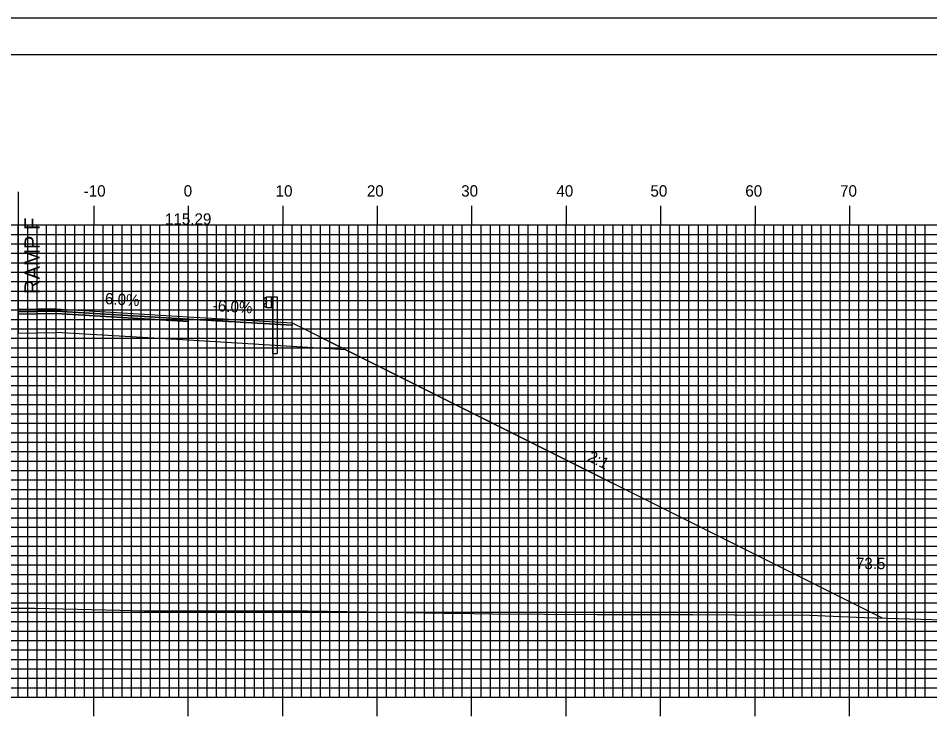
# Model space of a CAD drawing. Extents: x 855690 to 856034, y 364366 to 364586.
# Drawn here: x 855838.3 to 855934.8, y 364511.3 to 364585.7 of the extents above; entities that cross this region are included whole.
import ezdxf

# ---------------------------------------------------------------- set-up
doc = ezdxf.new("R2010")
doc.units = 0
for name, color, linetype in [('ANNOTATION', 7, 'Continuous'), ('BORDER', 7, 'Continuous'), ('D_Guardrail_Beam_Rt', 7, 'Continuous'), ('D_Roadway_Centerline', 7, 'Continuous'), ('D_Roadway_Centerline_Text', 7, 'Continuous'), ('D_Roadway_Edge_Shoulder', 7, 'Continuous'), ('D_Roadway_Edge_TW', 7, 'Continuous'), ('D_Roadway_Pavement', 7, 'Continuous'), ('D_Roadway_SlopeLines', 7, 'Continuous'), ('D_Roadway_SubGrade', 7, 'Continuous'), ('D_Text_Standard', 7, 'Continuous'), ('H_V ANNOTATION', 7, 'Continuous'), ('MAJOR', 7, 'Continuous'), ('MINOR', 7, 'Continuous'), ('PLOT BOUNDARY', 7, 'Continuous'), ('S_Roadway_Centerline', 7, 'Continuous')]:
    doc.layers.add(name, color=color, linetype=linetype)

msp = doc.modelspace()

# ---------------------------------------------------------------- linework, layer by layer
at = {"layer": 'BORDER'}
msp.add_lwpolyline([(855706.683, 364371.787), (856026.683, 364371.787), (856026.683, 364581.787), (855706.683, 364581.787)], close=True, dxfattribs=at)
at = {"layer": 'D_Guardrail_Beam_Rt'}
for p, q in [((855864.464, 364556.072), (855864.32, 364555.972)), ((855864.32, 364555.829), (855864.516, 364555.692)), ((855864.554, 364556.093), (855864.48, 364556.078)), ((855864.554, 364556.176), (855865.241, 364556.176)), ((855864.554, 364555.01), (855864.554, 364556.176)), ((855865.075, 364556.176), (855865.075, 364555.01)), ((855865.179, 364556.176), (855865.179, 364555.01)), ((855865.241, 364556.176), (855865.712, 364556.176)), ((855865.241, 364556.176), (855865.241, 364555.01)), ((855865.712, 364556.176), (855865.712, 364550.176)), ((855864.516, 364555.493), (855864.32, 364555.357)), ((855864.32, 364555.214), (855864.464, 364555.114)), ((855864.48, 364555.107), (855864.554, 364555.093)), ((855864.549, 364555.628), (855864.549, 364555.558)), ((855865.241, 364555.01), (855864.554, 364555.01)), ((855865.221, 364550.176), (855865.221, 364555.01)), ((855865.221, 364550.176), (855865.712, 364550.176))]:
    msp.add_line(p, q, dxfattribs=at)
for centre, major_axis, start_param, end_param in [((855864.371, 364555.9), (-0.0877, 0), 5.323254, 7.243116), ((855864.488, 364556.038), (-0.0417, 0), 4.907132, 5.323254), ((855864.371, 364555.286), (-0.0877, 0), 5.323254, 7.243116), ((855864.488, 364555.148), (-0.0417, 0), 0.959931, 1.376053), ((855864.471, 364555.628), (0.0789, 0), 0, 0.959931), ((855864.471, 364555.558), (0.0789, 0), 5.323254, 6.283185)]:
    msp.add_ellipse(centre, major_axis=major_axis, ratio=0.995501, start_param=start_param, end_param=end_param, dxfattribs=at)
at = {"layer": 'D_Roadway_Centerline'}
msp.add_lwpolyline([(855838.283, 364554.833), (855842.283, 364554.913), (855856.283, 364554.073), (855864.283, 364553.593), (855867.283, 364553.413), (855872.965, 364550.572), (855929.752, 364522.178)], dxfattribs=at)
at = {"layer": 'D_Roadway_Edge_Shoulder'}
for points in [[(855842.283, 364554.913), (855838.283, 364554.833), (855838.283, 364554.583), (855842.283, 364554.663)], [(855856.283, 364554.073), (855864.283, 364553.593), (855864.283, 364553.593), (855867.283, 364553.413), (855867.283, 364553.163), (855856.283, 364553.823)]]:
    msp.add_lwpolyline(points, close=True, dxfattribs=at)
at = {"layer": 'D_Roadway_Edge_TW'}
msp.add_lwpolyline([(855842.283, 364554.913), (855856.283, 364554.073), (855856.283, 364553.823), (855842.283, 364554.663)], close=True, dxfattribs=at)
at = {"layer": 'D_Roadway_Pavement'}
for points in [[(855842.283, 364554.663), (855838.283, 364554.583), (855838.283, 364554.333), (855842.283, 364554.413)], [(855842.283, 364554.663), (855856.283, 364553.823), (855856.283, 364553.573), (855842.283, 364554.413)]]:
    msp.add_lwpolyline(points, close=True, dxfattribs=at)
msp.add_lwpolyline([(855856.283, 364553.823), (855856.283, 364553.573)], dxfattribs=at)
msp.add_lwpolyline([(855856.283, 364553.823), (855856.283, 364553.573)], dxfattribs=at)
at = {"layer": 'D_Roadway_SlopeLines'}
msp.add_lwpolyline([(855867.283, 364553.413), (855929.752, 364522.178)], dxfattribs=at)
at = {"layer": 'D_Roadway_SubGrade'}
msp.add_line((855838.283, 364567.29), (855838.283, 364552.333), dxfattribs=at)
for points in [[(855842.283, 364554.413), (855838.283, 364554.333), (855838.283, 364554.583), (855838.283, 364554.833), (855838.283, 364552.333), (855842.283, 364552.413)], [(855842.283, 364554.413), (855856.283, 364553.573), (855856.283, 364551.573), (855842.283, 364552.413)], [(855856.283, 364553.573), (855856.283, 364553.823), (855867.283, 364553.163), (855867.283, 364553.413), (855872.965, 364550.572), (855856.283, 364551.573)]]:
    msp.add_lwpolyline(points, close=True, dxfattribs=at)
at = {"layer": 'MAJOR'}
for p, q in [((855846.283, 364565.791), (855846.283, 364563.787)), ((855856.283, 364565.791), (855856.283, 364563.787)), ((855866.283, 364565.791), (855866.283, 364563.787)), ((855876.283, 364565.791), (855876.283, 364563.787)), ((855886.283, 364565.791), (855886.283, 364563.787)), ((855896.283, 364565.791), (855896.283, 364563.787)), ((855906.283, 364565.791), (855906.283, 364563.787)), ((855916.283, 364565.791), (855916.283, 364563.787)), ((855926.283, 364565.791), (855926.283, 364563.787)), ((855716.283, 364563.787), (855996.283, 364563.787)), ((855716.283, 364563.787), (855996.283, 364563.787)), ((855846.283, 364513.787), (855846.283, 364563.787)), ((855856.283, 364513.787), (855856.283, 364563.787)), ((855866.283, 364513.787), (855866.283, 364563.787)), ((855876.283, 364513.787), (855876.283, 364563.787)), ((855886.283, 364513.787), (855886.283, 364563.787)), ((855896.283, 364513.787), (855896.283, 364563.787)), ((855906.283, 364513.787), (855906.283, 364563.787)), ((855916.283, 364513.787), (855916.283, 364563.787)), ((855926.283, 364513.787), (855926.283, 364563.787)), ((855716.283, 364558.787), (855996.283, 364558.787)), ((855716.283, 364553.787), (855996.283, 364553.787)), ((855716.283, 364548.787), (855996.283, 364548.787)), ((855716.283, 364543.787), (855996.283, 364543.787)), ((855716.283, 364538.787), (855996.283, 364538.787)), ((855716.283, 364533.787), (855996.283, 364533.787)), ((855716.283, 364528.787), (855996.283, 364528.787)), ((855716.283, 364523.787), (855996.283, 364523.787)), ((855716.283, 364518.787), (855996.283, 364518.787)), ((855716.283, 364513.787), (855996.283, 364513.787)), ((855716.283, 364513.787), (855996.283, 364513.787)), ((855846.283, 364511.783), (855846.283, 364513.787)), ((855856.283, 364511.783), (855856.283, 364513.787)), ((855866.283, 364511.783), (855866.283, 364513.787)), ((855876.283, 364511.783), (855876.283, 364513.787)), ((855886.283, 364511.783), (855886.283, 364513.787)), ((855896.283, 364511.783), (855896.283, 364513.787)), ((855906.283, 364511.783), (855906.283, 364513.787)), ((855916.283, 364511.783), (855916.283, 364513.787)), ((855926.283, 364511.783), (855926.283, 364513.787))]:
    msp.add_line(p, q, dxfattribs=at)
at = {"layer": 'MINOR'}
for p, q in [((855838.283, 364513.787), (855838.283, 364563.787)), ((855839.283, 364513.787), (855839.283, 364563.787)), ((855840.283, 364513.787), (855840.283, 364563.787)), ((855841.283, 364513.787), (855841.283, 364563.787)), ((855842.283, 364513.787), (855842.283, 364563.787)), ((855843.283, 364513.787), (855843.283, 364563.787)), ((855844.283, 364513.787), (855844.283, 364563.787)), ((855845.283, 364513.787), (855845.283, 364563.787)), ((855847.283, 364513.787), (855847.283, 364563.787)), ((855848.283, 364513.787), (855848.283, 364563.787)), ((855849.283, 364513.787), (855849.283, 364563.787)), ((855850.283, 364513.787), (855850.283, 364563.787)), ((855851.283, 364513.787), (855851.283, 364563.787)), ((855852.283, 364513.787), (855852.283, 364563.787)), ((855853.283, 364513.787), (855853.283, 364563.787)), ((855854.283, 364513.787), (855854.283, 364563.787)), ((855855.283, 364513.787), (855855.283, 364563.787)), ((855857.283, 364513.787), (855857.283, 364563.787)), ((855858.283, 364513.787), (855858.283, 364563.787)), ((855859.283, 364513.787), (855859.283, 364563.787)), ((855860.283, 364513.787), (855860.283, 364563.787)), ((855861.283, 364513.787), (855861.283, 364563.787)), ((855862.283, 364513.787), (855862.283, 364563.787)), ((855863.283, 364513.787), (855863.283, 364563.787)), ((855864.283, 364513.787), (855864.283, 364563.787)), ((855865.283, 364513.787), (855865.283, 364563.787)), ((855867.283, 364513.787), (855867.283, 364563.787)), ((855868.283, 364513.787), (855868.283, 364563.787)), ((855869.283, 364513.787), (855869.283, 364563.787)), ((855870.283, 364513.787), (855870.283, 364563.787)), ((855871.283, 364513.787), (855871.283, 364563.787)), ((855872.283, 364513.787), (855872.283, 364563.787)), ((855873.283, 364513.787), (855873.283, 364563.787)), ((855874.283, 364513.787), (855874.283, 364563.787)), ((855875.283, 364513.787), (855875.283, 364563.787)), ((855877.283, 364513.787), (855877.283, 364563.787)), ((855878.283, 364513.787), (855878.283, 364563.787)), ((855879.283, 364513.787), (855879.283, 364563.787)), ((855880.283, 364513.787), (855880.283, 364563.787)), ((855881.283, 364513.787), (855881.283, 364563.787)), ((855882.283, 364513.787), (855882.283, 364563.787)), ((855883.283, 364513.787), (855883.283, 364563.787)), ((855884.283, 364513.787), (855884.283, 364563.787)), ((855885.283, 364513.787), (855885.283, 364563.787)), ((855887.283, 364513.787), (855887.283, 364563.787)), ((855888.283, 364513.787), (855888.283, 364563.787)), ((855889.283, 364513.787), (855889.283, 364563.787)), ((855890.283, 364513.787), (855890.283, 364563.787)), ((855891.283, 364513.787), (855891.283, 364563.787)), ((855892.283, 364513.787), (855892.283, 364563.787)), ((855893.283, 364513.787), (855893.283, 364563.787)), ((855894.283, 364513.787), (855894.283, 364563.787)), ((855895.283, 364513.787), (855895.283, 364563.787)), ((855897.283, 364513.787), (855897.283, 364563.787)), ((855898.283, 364513.787), (855898.283, 364563.787)), ((855899.283, 364513.787), (855899.283, 364563.787)), ((855900.283, 364513.787), (855900.283, 364563.787)), ((855901.283, 364513.787), (855901.283, 364563.787)), ((855902.283, 364513.787), (855902.283, 364563.787)), ((855903.283, 364513.787), (855903.283, 364563.787)), ((855904.283, 364513.787), (855904.283, 364563.787)), ((855905.283, 364513.787), (855905.283, 364563.787)), ((855907.283, 364513.787), (855907.283, 364563.787)), ((855908.283, 364513.787), (855908.283, 364563.787)), ((855909.283, 364513.787), (855909.283, 364563.787)), ((855910.283, 364513.787), (855910.283, 364563.787)), ((855911.283, 364513.787), (855911.283, 364563.787)), ((855912.283, 364513.787), (855912.283, 364563.787)), ((855913.283, 364513.787), (855913.283, 364563.787)), ((855914.283, 364513.787), (855914.283, 364563.787)), ((855915.283, 364513.787), (855915.283, 364563.787)), ((855917.283, 364513.787), (855917.283, 364563.787)), ((855918.283, 364513.787), (855918.283, 364563.787)), ((855919.283, 364513.787), (855919.283, 364563.787)), ((855920.283, 364513.787), (855920.283, 364563.787)), ((855921.283, 364513.787), (855921.283, 364563.787)), ((855922.283, 364513.787), (855922.283, 364563.787)), ((855923.283, 364513.787), (855923.283, 364563.787)), ((855924.283, 364513.787), (855924.283, 364563.787)), ((855925.283, 364513.787), (855925.283, 364563.787)), ((855927.283, 364513.787), (855927.283, 364563.787)), ((855928.283, 364513.787), (855928.283, 364563.787)), ((855929.283, 364513.787), (855929.283, 364563.787)), ((855930.283, 364513.787), (855930.283, 364563.787)), ((855931.283, 364513.787), (855931.283, 364563.787)), ((855932.283, 364513.787), (855932.283, 364563.787)), ((855933.283, 364513.787), (855933.283, 364563.787)), ((855934.283, 364513.787), (855934.283, 364563.787)), ((855716.283, 364562.787), (855996.283, 364562.787)), ((855716.283, 364561.787), (855996.283, 364561.787)), ((855716.283, 364560.787), (855996.283, 364560.787)), ((855716.283, 364559.787), (855996.283, 364559.787)), ((855716.283, 364557.787), (855996.283, 364557.787)), ((855716.283, 364556.787), (855996.283, 364556.787)), ((855716.283, 364555.787), (855996.283, 364555.787)), ((855716.283, 364554.787), (855996.283, 364554.787)), ((855716.283, 364552.787), (855996.283, 364552.787)), ((855716.283, 364551.787), (855996.283, 364551.787)), ((855716.283, 364550.787), (855996.283, 364550.787)), ((855716.283, 364549.787), (855996.283, 364549.787)), ((855716.283, 364547.787), (855996.283, 364547.787)), ((855716.283, 364546.787), (855996.283, 364546.787)), ((855716.283, 364545.787), (855996.283, 364545.787)), ((855716.283, 364544.787), (855996.283, 364544.787)), ((855716.283, 364542.787), (855996.283, 364542.787)), ((855716.283, 364541.787), (855996.283, 364541.787)), ((855716.283, 364540.787), (855996.283, 364540.787)), ((855716.283, 364539.787), (855996.283, 364539.787)), ((855716.283, 364537.787), (855996.283, 364537.787)), ((855716.283, 364536.787), (855996.283, 364536.787)), ((855716.283, 364535.787), (855996.283, 364535.787)), ((855716.283, 364534.787), (855996.283, 364534.787)), ((855716.283, 364532.787), (855996.283, 364532.787)), ((855716.283, 364531.787), (855996.283, 364531.787)), ((855716.283, 364530.787), (855996.283, 364530.787)), ((855716.283, 364529.787), (855996.283, 364529.787)), ((855716.283, 364527.787), (855996.283, 364527.787)), ((855716.283, 364526.787), (855996.283, 364526.787)), ((855716.283, 364525.787), (855996.283, 364525.787)), ((855716.283, 364524.787), (855996.283, 364524.787)), ((855716.283, 364522.787), (855996.283, 364522.787)), ((855716.283, 364521.787), (855996.283, 364521.787)), ((855716.283, 364520.787), (855996.283, 364520.787)), ((855716.283, 364519.787), (855996.283, 364519.787)), ((855716.283, 364517.787), (855996.283, 364517.787)), ((855716.283, 364516.787), (855996.283, 364516.787)), ((855716.283, 364515.787), (855996.283, 364515.787)), ((855716.283, 364514.787), (855996.283, 364514.787))]:
    msp.add_line(p, q, dxfattribs=at)
at = {"layer": 'PLOT BOUNDARY'}
msp.add_lwpolyline([(855690.496, 364365.669), (856030.496, 364365.669), (856030.496, 364585.669), (855690.496, 364585.669)], close=True, dxfattribs=at)
at = {"layer": 'S_Roadway_Centerline'}
msp.add_lwpolyline([(855828.741, 364523.198), (855840.05, 364523.229), (855849.051, 364522.999), (855851.606, 364522.95), (855855.372, 364522.927), (855868.928, 364522.933), (855883.413, 364522.68), (855886.491, 364522.66), (855888.478, 364522.631), (855899.564, 364522.553), (855909.683, 364522.536), (855914.095, 364522.505), (855922.053, 364522.466), (855927.888, 364522.234), (855942.154, 364521.808), (855948.743, 364521.684), (855956.778, 364521.727), (855968.853, 364521.657), (855969.908, 364521.695), (855988.005, 364521.845), (855992.943, 364521.563), (855996.283, 364521.629)], dxfattribs=at)

# ---------------------------------------------------------------- texts
at = {"layer": 'ANNOTATION'}
for s, height, rotation, p in [('RAMP F', 1.6, 90, (855840.544, 364556.47)), ('6.0%', 1.2, 356.56637, (855847.437, 364555.407)), ('-6.0%', 1.2, 356.56637, (855858.856, 364554.676)), ('2:1', 1.2, 333.43495, (855898.452, 364538.865))]:
    msp.add_text(s, height=height, rotation=rotation, dxfattribs=at).set_placement(p)
at = {"layer": 'D_Roadway_Centerline_Text'}
msp.add_text('115.29', height=1.2, dxfattribs=at).set_placement((855853.822, 364563.81))
at = {"layer": 'D_Text_Standard'}
msp.add_text("73.5'", height=1.2, dxfattribs=at).set_placement((855926.967, 364527.346))
at = {"layer": 'H_V ANNOTATION'}
for s, p in [('-10', (855845.213, 364566.787)), ('0', (855855.801, 364566.787)), ('10', (855865.534, 364566.787)), ('20', (855875.191, 364566.787)), ('30', (855885.18, 364566.787)), ('40', (855895.255, 364566.787)), ('50', (855905.212, 364566.787)), ('60', (855915.255, 364566.787)), ('70', (855925.287, 364566.787))]:
    msp.add_text(s, height=1.2, dxfattribs=at).set_placement(p)

doc.saveas('drawing.dxf')
